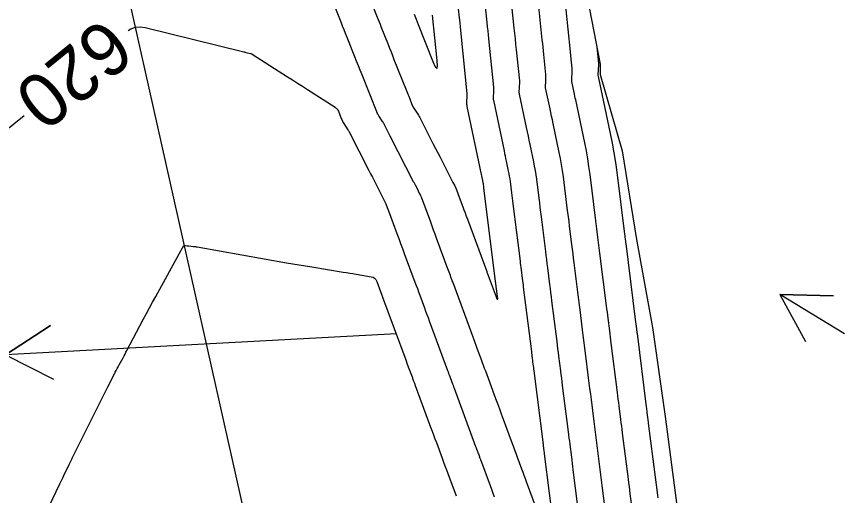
# Model space of a CAD drawing. Extents: x 954385 to 988206, y 1868364 to 1924553.
# Drawn here: x 958114.8 to 958207.1, y 1918400.9 to 1918454.4 of the extents above; entities that cross this region are included whole.
import ezdxf

# ---------------------------------------------------------------- set-up
doc = ezdxf.new("R2010")
doc.units = 0
for name, color, linetype in [('Default', 7, 'Continuous'), ('Ex_Contour Labels', 7, 'Continuous'), ('Ex_Major Contours', 7, 'Continuous'), ('Ex_Minor Contours', 7, 'Continuous'), ('Perimeter', 7, 'Continuous'), ('Slopes', 7, 'Continuous')]:
    doc.layers.add(name, color=color, linetype=linetype)

msp = doc.modelspace()

# ---------------------------------------------------------------- linework, layer by layer
at = {"layer": 'Default'}
msp.add_line((958200.602, 1918129.717), (957843.865, 1919719.405), dxfattribs=at)
at = {"layer": 'Ex_Major Contours'}
for points in [[(958177.618, 1918397.909), (958176.876, 1918403.746), (958176.831, 1918404.101), (958176.786, 1918404.456), (958176.741, 1918404.81), (958176.696, 1918405.165), (958176.516, 1918406.584), (958176.471, 1918406.938), (958176.426, 1918407.293), (958176.381, 1918407.648), (958176.336, 1918408.003), (958175.683, 1918413.17), (958175.632, 1918413.579), (958175.58, 1918413.988), (958175.528, 1918414.397), (958175.477, 1918414.806), (958175.271, 1918416.442), (958175.219, 1918416.851), (958175.168, 1918417.26), (958175.116, 1918417.669), (958175.065, 1918418.078), (958174.496, 1918422.618), (958174.439, 1918423.079), (958174.381, 1918423.54), (958174.323, 1918424.001), (958174.265, 1918424.462), (958174.034, 1918426.306), (958173.976, 1918426.767), (958173.919, 1918427.228), (958173.861, 1918427.689), (958173.803, 1918428.15), (958173.322, 1918431.998), (958173.256, 1918432.518), (958173.191, 1918433.038), (958173.126, 1918433.558), (958173.061, 1918434.077), (958172.791, 1918436.223), (958172.725, 1918436.709), (958172.649, 1918437.193), (958172.563, 1918437.675), (958172.467, 1918438.156), (958172.064, 1918440.075), (958171.963, 1918440.555), (958171.862, 1918441.035), (958171.761, 1918441.515), (958171.66, 1918441.994), (958170.874, 1918445.729), (958170.861, 1918445.803), (958170.853, 1918445.878), (958170.849, 1918445.953), (958170.851, 1918446.028), (958170.868, 1918446.34), (958170.872, 1918446.411), (958170.875, 1918446.482), (958170.879, 1918446.553), (958170.883, 1918446.624), (958170.899, 1918446.908), (958170.901, 1918446.979), (958170.901, 1918447.05), (958170.898, 1918447.12), (958170.892, 1918447.191), (958170.535, 1918450.669), (958170.473, 1918451.272), (958170.411, 1918451.876), (958170.349, 1918452.479), (958170.288, 1918453.082), (958169.989, 1918455.996)], [(958127.216, 1918452.819), (958127.51, 1918453.011), (958128.012, 1918453.192), (958128.544, 1918453.243), (958129.104, 1918453.165), (958140.098, 1918450.441), (958140.158, 1918450.426), (958140.217, 1918450.412), (958140.276, 1918450.397), (958140.335, 1918450.382), (958140.906, 1918450.238), (958140.941, 1918450.228), (958140.975, 1918450.215), (958141.008, 1918450.199), (958141.04, 1918450.18), (958144.969, 1918447.664), (958145.528, 1918447.306), (958146.086, 1918446.948), (958146.645, 1918446.591), (958147.203, 1918446.233), (958150.291, 1918444.255), (958150.413, 1918444.163), (958150.516, 1918444.056), (958150.601, 1918443.934), (958150.668, 1918443.797), (958150.982, 1918443.007), (958151.029, 1918442.889), (958151.107, 1918442.692), (958151.123, 1918442.653), (958151.142, 1918442.615), (958151.162, 1918442.578), (958151.185, 1918442.543), (958151.713, 1918441.741), (958151.74, 1918441.7), (958151.785, 1918441.632), (958151.793, 1918441.618), (958151.802, 1918441.604), (958151.81, 1918441.59), (958151.817, 1918441.576), (958154.071, 1918437.173), (958154.261, 1918436.801), (958154.452, 1918436.429), (958154.643, 1918436.056), (958154.833, 1918435.684), (958155.596, 1918434.195), (958155.781, 1918433.821), (958155.954, 1918433.441), (958156.116, 1918433.056), (958156.266, 1918432.667), (958157.202, 1918430.132), (958157.406, 1918429.579), (958157.61, 1918429.026), (958157.815, 1918428.473), (958158.019, 1918427.92), (958159.206, 1918424.706), (958159.339, 1918424.346), (958159.472, 1918423.986), (958159.605, 1918423.627), (958159.737, 1918423.267), (958160.268, 1918421.828), (958160.4, 1918421.468), (958160.533, 1918421.109), (958160.666, 1918420.749), (958160.798, 1918420.389), (958162.838, 1918414.855), (958162.9, 1918414.688), (958162.962, 1918414.521), (958163.023, 1918414.353), (958163.085, 1918414.186), (958163.332, 1918413.517), (958163.394, 1918413.349), (958163.456, 1918413.182), (958163.517, 1918413.014), (958163.579, 1918412.847), (958165.975, 1918406.353), (958166.026, 1918406.214), (958166.078, 1918406.074), (958166.181, 1918405.795), (958166.232, 1918405.655), (958166.284, 1918405.515), (958166.398, 1918405.206), (958166.425, 1918405.131), (958166.453, 1918405.056), (958166.481, 1918404.981), (958166.508, 1918404.906), (958167.587, 1918401.99), (958167.743, 1918401.57), (958167.898, 1918401.149), (958168.053, 1918400.729)], [(958113.284, 1918441.448), (958115.588, 1918443.343)]]:
    msp.add_lwpolyline(points, dxfattribs=at)
at = {"layer": 'Ex_Minor Contours'}
for points in [[(958153.529, 1918457.983), (958154.999, 1918454.296), (958155.103, 1918454.036), (958155.207, 1918453.775), (958155.311, 1918453.514), (958155.415, 1918453.254), (958156.204, 1918451.268), (958156.37, 1918450.85), (958156.536, 1918450.432), (958156.702, 1918450.014), (958156.868, 1918449.596), (958158.213, 1918446.207), (958158.286, 1918446.023), (958158.359, 1918445.839), (958158.432, 1918445.654), (958158.505, 1918445.47), (958158.936, 1918444.386), (958158.94, 1918444.376), (958158.945, 1918444.366), (958158.95, 1918444.356), (958158.956, 1918444.347), (958158.992, 1918444.292), (958159.004, 1918444.273), (958159.454, 1918443.59), (958159.53, 1918443.472), (958159.602, 1918443.352), (958159.67, 1918443.23), (958159.736, 1918443.107), (958161.253, 1918440.142), (958161.506, 1918439.648), (958161.759, 1918439.154), (958162.012, 1918438.66), (958162.265, 1918438.166), (958163.447, 1918435.859), (958163.61, 1918435.528), (958163.763, 1918435.194), (958163.906, 1918434.854), (958164.038, 1918434.511), (958164.549, 1918433.127), (958164.677, 1918432.782), (958164.804, 1918432.436), (958164.932, 1918432.09), (958165.06, 1918431.744), (958167.212, 1918425.917), (958167.245, 1918425.828), (958167.278, 1918425.738), (958167.311, 1918425.649), (958167.344, 1918425.56), (958167.541, 1918425.024), (958167.607, 1918424.845), (958168.261, 1918423.071), (958168.361, 1918422.829), (958168.42, 1918422.754), (958168.438, 1918422.847), (958168.415, 1918423.108), (958168.092, 1918425.689), (958168.057, 1918425.965), (958166.934, 1918434.938), (958166.922, 1918435.033), (958166.91, 1918435.127), (958166.899, 1918435.222), (958166.887, 1918435.316), (958166.838, 1918435.706), (958166.826, 1918435.794), (958166.812, 1918435.882), (958166.796, 1918435.97), (958166.779, 1918436.057), (958166.706, 1918436.406), (958166.669, 1918436.58), (958166.632, 1918436.754), (958165.04, 1918444.319), (958165.018, 1918444.442), (958165.005, 1918444.565), (958164.999, 1918444.689), (958165.002, 1918444.813), (958165.04, 1918445.517), (958165.045, 1918445.605), (958165.05, 1918445.692), (958165.05, 1918445.714), (958165.05, 1918445.736), (958165.049, 1918445.758), (958165.047, 1918445.78), (958164.285, 1918453.208), (958164.233, 1918453.717), (958164.181, 1918454.226), (958164.076, 1918455.245)], [(958183.443, 1918399.453), (958183.237, 1918401.073), (958183.185, 1918401.478), (958183.134, 1918401.883), (958183.083, 1918402.288), (958183.031, 1918402.693), (958182.376, 1918407.849), (958182.328, 1918408.228), (958182.28, 1918408.607), (958182.232, 1918408.986), (958182.184, 1918409.365), (958181.992, 1918410.881), (958181.945, 1918411.26), (958181.897, 1918411.639), (958181.849, 1918412.018), (958181.801, 1918412.398), (958181.111, 1918417.876), (958181.067, 1918418.225), (958181.023, 1918418.574), (958180.979, 1918418.923), (958180.935, 1918419.272), (958180.761, 1918420.668), (958180.717, 1918421.017), (958180.673, 1918421.366), (958180.629, 1918421.715), (958180.586, 1918422.064), (958179.849, 1918427.941), (958179.811, 1918428.241), (958179.774, 1918428.542), (958179.736, 1918428.843), (958179.698, 1918429.144), (958179.548, 1918430.347), (958179.51, 1918430.647), (958179.472, 1918430.948), (958179.435, 1918431.249), (958179.397, 1918431.55), (958178.744, 1918436.741), (958178.624, 1918437.624), (958178.486, 1918438.504), (958178.33, 1918439.381), (958178.155, 1918440.255), (958177.144, 1918445.064), (958177.1, 1918445.277), (958177.055, 1918445.49), (958177.01, 1918445.702), (958176.965, 1918445.915), (958176.708, 1918447.139), (958176.703, 1918447.165), (958176.7, 1918447.191), (958176.699, 1918447.217), (958176.7, 1918447.244), (958176.707, 1918447.377), (958176.711, 1918447.456), (958176.748, 1918448.123), (958176.752, 1918448.243), (958176.752, 1918448.363), (958176.746, 1918448.483), (958176.736, 1918448.603), (958176.632, 1918449.616), (958176.59, 1918450.034), (958176.547, 1918450.452), (958175.764, 1918458.086)], [(958180.48, 1918399.077), (958180.112, 1918401.974), (958180.036, 1918402.572), (958179.96, 1918403.169), (958179.884, 1918403.767), (958179.808, 1918404.364), (958179.504, 1918406.755), (958179.429, 1918407.353), (958179.353, 1918407.95), (958179.277, 1918408.548), (958179.202, 1918409.145), (958178.892, 1918411.598), (958178.815, 1918412.206), (958178.738, 1918412.814), (958178.662, 1918413.422), (958178.585, 1918414.03), (958178.238, 1918416.783), (958178.167, 1918417.35), (958178.095, 1918417.917), (958178.024, 1918418.484), (958177.953, 1918419.051), (958177.669, 1918421.319), (958177.598, 1918421.886), (958177.527, 1918422.453), (958177.456, 1918423.02), (958177.385, 1918423.587), (958176.975, 1918426.858), (958176.91, 1918427.372), (958176.846, 1918427.885), (958176.782, 1918428.399), (958176.718, 1918428.912), (958176.46, 1918430.966), (958176.396, 1918431.479), (958176.332, 1918431.993), (958176.267, 1918432.506), (958176.203, 1918433.02), (958175.768, 1918436.482), (958175.675, 1918437.166), (958175.567, 1918437.848), (958175.446, 1918438.528), (958175.311, 1918439.205), (958174.63, 1918442.444), (958174.544, 1918442.853), (958174.458, 1918443.262), (958174.372, 1918443.671), (958174.286, 1918444.08), (958173.791, 1918446.434), (958173.782, 1918446.484), (958173.776, 1918446.534), (958173.774, 1918446.585), (958173.775, 1918446.636), (958173.786, 1918446.84), (958173.792, 1918446.943), (958173.798, 1918447.045), (958173.823, 1918447.516), (958173.827, 1918447.611), (958173.826, 1918447.706), (958173.822, 1918447.802), (958173.814, 1918447.897), (958173.584, 1918450.143), (958173.542, 1918450.549), (958173.5, 1918450.955), (958173.459, 1918451.361), (958173.417, 1918451.767), (958172.876, 1918457.041)], [(958173.779, 1918396.679), (958171.665, 1918402.393), (958171.535, 1918402.747), (958171.404, 1918403.101), (958171.273, 1918403.455), (958171.142, 1918403.808), (958170.618, 1918405.224), (958170.487, 1918405.578), (958170.357, 1918405.931), (958170.226, 1918406.285), (958170.095, 1918406.639), (958169.085, 1918409.377), (958168.873, 1918409.951), (958168.662, 1918410.525), (958168.45, 1918411.099), (958168.238, 1918411.673), (958167.097, 1918414.763), (958166.98, 1918415.08), (958166.863, 1918415.396), (958166.746, 1918415.713), (958166.629, 1918416.03), (958166.162, 1918417.298), (958166.045, 1918417.615), (958165.928, 1918417.932), (958165.811, 1918418.249), (958165.695, 1918418.566), (958163.417, 1918424.745), (958163.374, 1918424.862), (958163.331, 1918424.979), (958163.223, 1918425.271), (958163.158, 1918425.446), (958162.742, 1918426.573), (958162.666, 1918426.78), (958162.589, 1918426.987), (958162.513, 1918427.194), (958162.436, 1918427.402), (958161.612, 1918429.637), (958161.449, 1918430.079), (958161.286, 1918430.521), (958161.123, 1918430.962), (958160.96, 1918431.404), (958159.93, 1918434.191), (958159.904, 1918434.259), (958159.876, 1918434.325), (958159.846, 1918434.391), (958159.814, 1918434.456), (958159.649, 1918434.777), (958159.55, 1918434.97), (958159.252, 1918435.553), (958159.148, 1918435.756), (958159.096, 1918435.857), (958156.445, 1918441.033), (958156.371, 1918441.178), (958156.297, 1918441.323), (958156.223, 1918441.467), (958156.149, 1918441.612), (958155.807, 1918442.279), (958155.754, 1918442.379), (958155.699, 1918442.477), (958155.641, 1918442.574), (958155.581, 1918442.669), (958155.251, 1918443.172), (958155.23, 1918443.204), (958155.209, 1918443.236), (958155.188, 1918443.267), (958155.168, 1918443.299), (958155.084, 1918443.426), (958155.064, 1918443.458), (958155.045, 1918443.492), (958155.029, 1918443.526), (958155.014, 1918443.56), (958153.298, 1918447.878), (958153.099, 1918448.38), (958152.899, 1918448.882), (958152.7, 1918449.384), (958152.5, 1918449.887), (958151.64, 1918452.056), (958151.472, 1918452.478), (958151.304, 1918452.9), (958151.136, 1918453.322), (958150.968, 1918453.743), (958150.296, 1918455.43)], [(958167.044, 1918455.507), (958167.23, 1918453.7), (958167.276, 1918453.248), (958167.322, 1918452.796), (958167.369, 1918452.345), (958167.415, 1918451.893), (958167.97, 1918446.486), (958167.974, 1918446.439), (958167.976, 1918446.393), (958167.976, 1918446.347), (958167.974, 1918446.3), (958167.961, 1918446.068), (958167.956, 1918445.975), (958167.954, 1918445.928), (958167.926, 1918445.421), (958167.924, 1918445.321), (958167.929, 1918445.221), (958167.94, 1918445.122), (958167.957, 1918445.024), (958169.146, 1918439.374), (958169.206, 1918439.091), (958169.265, 1918438.807), (958169.325, 1918438.524), (958169.385, 1918438.24), (958169.623, 1918437.106), (958169.68, 1918436.822), (958169.73, 1918436.537), (958169.775, 1918436.251), (958169.814, 1918435.965), (958169.974, 1918434.697), (958170.012, 1918434.39), (958170.051, 1918434.082), (958170.089, 1918433.775), (958170.128, 1918433.468), (958170.93, 1918427.058), (958170.961, 1918426.814), (958170.991, 1918426.571), (958171.022, 1918426.328), (958171.052, 1918426.085), (958171.174, 1918425.113), (958171.204, 1918424.87), (958171.235, 1918424.627), (958171.265, 1918424.384), (958171.296, 1918424.141), (958172.195, 1918416.963), (958172.217, 1918416.783), (958172.24, 1918416.603), (958172.263, 1918416.423), (958172.285, 1918416.243), (958172.376, 1918415.522), (958172.399, 1918415.342), (958172.422, 1918415.162), (958172.444, 1918414.982), (958172.467, 1918414.802), (958173.47, 1918406.86), (958173.484, 1918406.748), (958173.499, 1918406.636), (958173.513, 1918406.524), (958173.527, 1918406.413), (958173.598, 1918405.854), (958173.626, 1918405.63), (958173.64, 1918405.519), (958174.757, 1918396.74)], [(958159.11, 1918454.651), (958159.339, 1918454.074), (958159.569, 1918453.497), (958161.211, 1918449.362), (958161.48, 1918448.766), (958161.646, 1918448.586), (958161.711, 1918448.823), (958161.674, 1918449.475), (958161.156, 1918454.523)], [(958179.483, 1918451.017), (958179.681, 1918449.09), (958179.686, 1918449.044), (958179.687, 1918449.032), (958179.687, 1918449.02), (958179.687, 1918449.009), (958179.687, 1918448.997), (958179.625, 1918447.864), (958179.624, 1918447.85), (958179.625, 1918447.843), (958179.658, 1918447.685), (958180.999, 1918441.304), (958181.213, 1918440.234), (958181.404, 1918439.159), (958181.574, 1918438.081), (958181.721, 1918436.999), (958182.591, 1918430.08), (958182.613, 1918429.904), (958182.635, 1918429.727), (958182.69, 1918429.287), (958182.712, 1918429.111), (958182.723, 1918429.023), (958183.786, 1918420.541), (958183.819, 1918420.279), (958183.852, 1918420.017), (958183.918, 1918419.493), (958183.934, 1918419.362), (958183.951, 1918419.231), (958183.967, 1918419.1), (958183.984, 1918418.969), (958185.017, 1918410.766), (958185.036, 1918410.615), (958185.055, 1918410.465), (958185.074, 1918410.315), (958185.093, 1918410.165), (958185.169, 1918409.564), (958185.188, 1918409.414), (958185.207, 1918409.264), (958185.226, 1918409.114), (958185.245, 1918408.964), (958186.267, 1918400.92), (958186.308, 1918400.596)], [(958116.819, 1918396.395), (958119.593, 1918402.173), (958119.703, 1918402.403), (958119.813, 1918402.633), (958119.924, 1918402.863), (958120.034, 1918403.094), (958120.618, 1918404.318), (958120.656, 1918404.397), (958120.694, 1918404.476), (958120.732, 1918404.554), (958120.77, 1918404.633), (958120.924, 1918404.948), (958120.962, 1918405.026), (958121.001, 1918405.105), (958121.04, 1918405.183), (958121.079, 1918405.261), (958124.507, 1918412.114), (958124.654, 1918412.408), (958124.801, 1918412.701), (958124.948, 1918412.995), (958125.095, 1918413.289), (958125.772, 1918414.639), (958125.876, 1918414.844), (958125.981, 1918415.048), (958126.088, 1918415.252), (958126.197, 1918415.454), (958126.635, 1918416.262), (958126.744, 1918416.465), (958126.852, 1918416.667), (958126.96, 1918416.87), (958127.067, 1918417.073), (958128.893, 1918420.546), (958129.234, 1918421.192), (958129.579, 1918421.836), (958129.926, 1918422.478), (958130.277, 1918423.119), (958133.109, 1918428.269), (958133.126, 1918428.297), (958133.142, 1918428.326), (958133.159, 1918428.354), (958133.177, 1918428.382), (958133.248, 1918428.494), (958133.266, 1918428.522), (958133.285, 1918428.549), (958133.303, 1918428.576), (958133.323, 1918428.603), (958133.432, 1918428.752), (958133.459, 1918428.781), (958133.49, 1918428.8), (958133.526, 1918428.809), (958133.565, 1918428.808), (958133.771, 1918428.779), (958133.819, 1918428.773), (958133.868, 1918428.766), (958133.916, 1918428.761), (958133.964, 1918428.755), (958134.497, 1918428.7), (958134.601, 1918428.688), (958134.706, 1918428.674), (958134.81, 1918428.658), (958134.914, 1918428.641), (958144.861, 1918426.881), (958145.566, 1918426.757), (958146.272, 1918426.637), (958146.979, 1918426.519), (958147.686, 1918426.405), (958151.213, 1918425.84), (958151.571, 1918425.782), (958151.928, 1918425.723), (958152.285, 1918425.664), (958152.642, 1918425.603), (958154.317, 1918425.316), (958154.531, 1918425.253), (958154.708, 1918425.145), (958154.846, 1918424.992), (958154.947, 1918424.793), (958155.405, 1918423.55), (958155.47, 1918423.374), (958155.552, 1918423.155), (958155.584, 1918423.067), (958155.6, 1918423.023), (958158.178, 1918416.031), (958158.354, 1918415.553), (958158.53, 1918415.076), (958158.882, 1918414.122), (958158.97, 1918413.883), (958159.058, 1918413.644), (958159.146, 1918413.406), (958159.234, 1918413.167), (958160.954, 1918408.506), (958161.114, 1918408.074), (958161.273, 1918407.641), (958161.433, 1918407.209), (958161.592, 1918406.776), (958162.231, 1918405.045), (958162.391, 1918404.613), (958162.55, 1918404.18), (958162.71, 1918403.748), (958162.87, 1918403.315), (958163.787, 1918400.837)]]:
    msp.add_lwpolyline(points, dxfattribs=at)
at = {"layer": 'Perimeter'}
msp.add_lwpolyline([(958166.174, 1918538.226), (958167.505, 1918528.276), (958168.873, 1918518.334), (958170.656, 1918508.486), (958172.595, 1918498.672), (958174.126, 1918488.767), (958175.694, 1918478.87), (958176.714, 1918468.85), (958177.967, 1918458.883), (958179.861, 1918449.059), (958179.867, 1918447.902), (958182.315, 1918439.361), (958183.913, 1918429.471), (958185.71, 1918419.626), (958187.127, 1918409.695), (958188.425, 1918399.738), (958190.025, 1918389.848), (958192.011, 1918380.045), (958194.127, 1918370.271), (958196.146, 1918360.475), (958197.733, 1918350.583), (958199.858, 1918340.811)], dxfattribs=at)
at = {"layer": 'Slopes'}
for points in [[(958207.131, 1918418.928), (958199.924, 1918423.336), (958205.922, 1918423.184), (958199.924, 1918423.336), (958202.791, 1918418.066)], [(958157.131, 1918418.928), (958113.53, 1918416.575), (958118.557, 1918419.851), (958113.53, 1918416.575), (958118.88, 1918413.859)]]:
    msp.add_lwpolyline(points, dxfattribs=at)

# ---------------------------------------------------------------- texts
at = {"layer": 'Ex_Contour Labels'}
msp.add_text('620', height=6, rotation=219.17685, dxfattribs=at).set_placement((958124.491, 1918454.468))

doc.saveas('drawing.dxf')
